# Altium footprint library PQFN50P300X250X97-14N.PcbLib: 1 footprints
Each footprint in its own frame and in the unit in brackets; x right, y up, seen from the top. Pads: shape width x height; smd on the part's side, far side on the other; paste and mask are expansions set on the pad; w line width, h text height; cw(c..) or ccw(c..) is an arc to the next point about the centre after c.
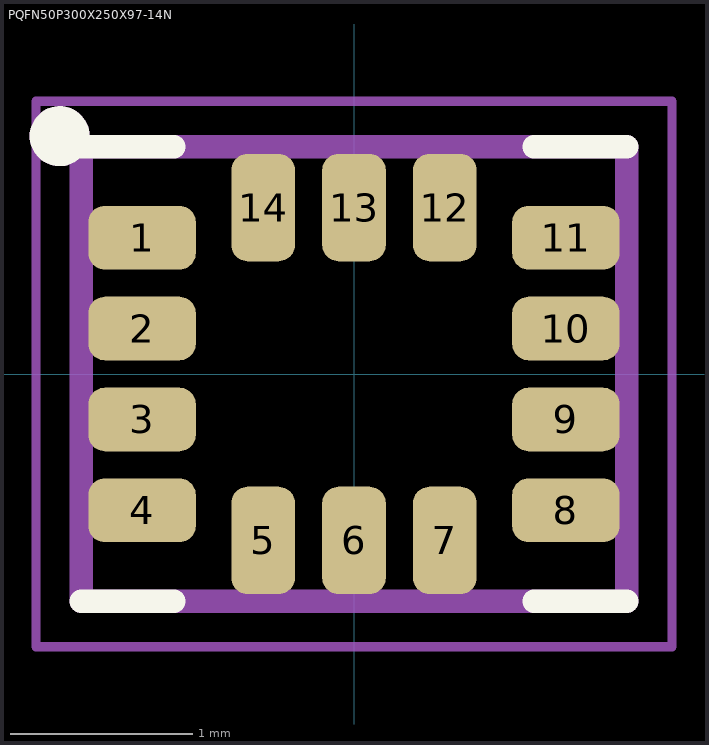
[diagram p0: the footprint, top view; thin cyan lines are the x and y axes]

## PQFN50P300X250X97-14N [mm]
pads (14):
  rrect50% 0.59x0.35 smd mask+0: 1(-1.165,0.75) 2(-1.165,0.25) 3(-1.165,-0.25) 4(-1.165,-0.75) 8(1.165,-0.75) 9(1.165,-0.25) 10(1.165,0.25) 11(1.165,0.75)
  rrect50% 0.35x0.59 smd mask+0: 5(-0.5,-0.915) 6(0,-0.915) 7(0.5,-0.915) 12(0.5,0.915) 13(0,0.915) 14(-0.5,0.915)
Top Overlay:
  circle w0.178: c-1.619,1.308 r0.076
  lines w0.127: -1.5,-1.25 -0.99,-1.25 ; -1.5,1.25 -0.99,1.25 ; 0.99,-1.25 1.5,-1.25 ; 0.99,1.25 1.5,1.25
Top Solder:
  drawing of 14 lines, arcs and shapes, not listed
Mechanical 13:
  circle w0.178: c-1.619,1.308 r0.076
  lines w0.127: -1.5,-1.25 -1.5,1.25 1.5,1.25 1.5,-1.25 -1.5,-1.25
Mechanical 15:
  lines w0.05: -1.75,-1.5 -1.75,1.5 1.75,1.5 1.75,-1.5 -1.75,-1.5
